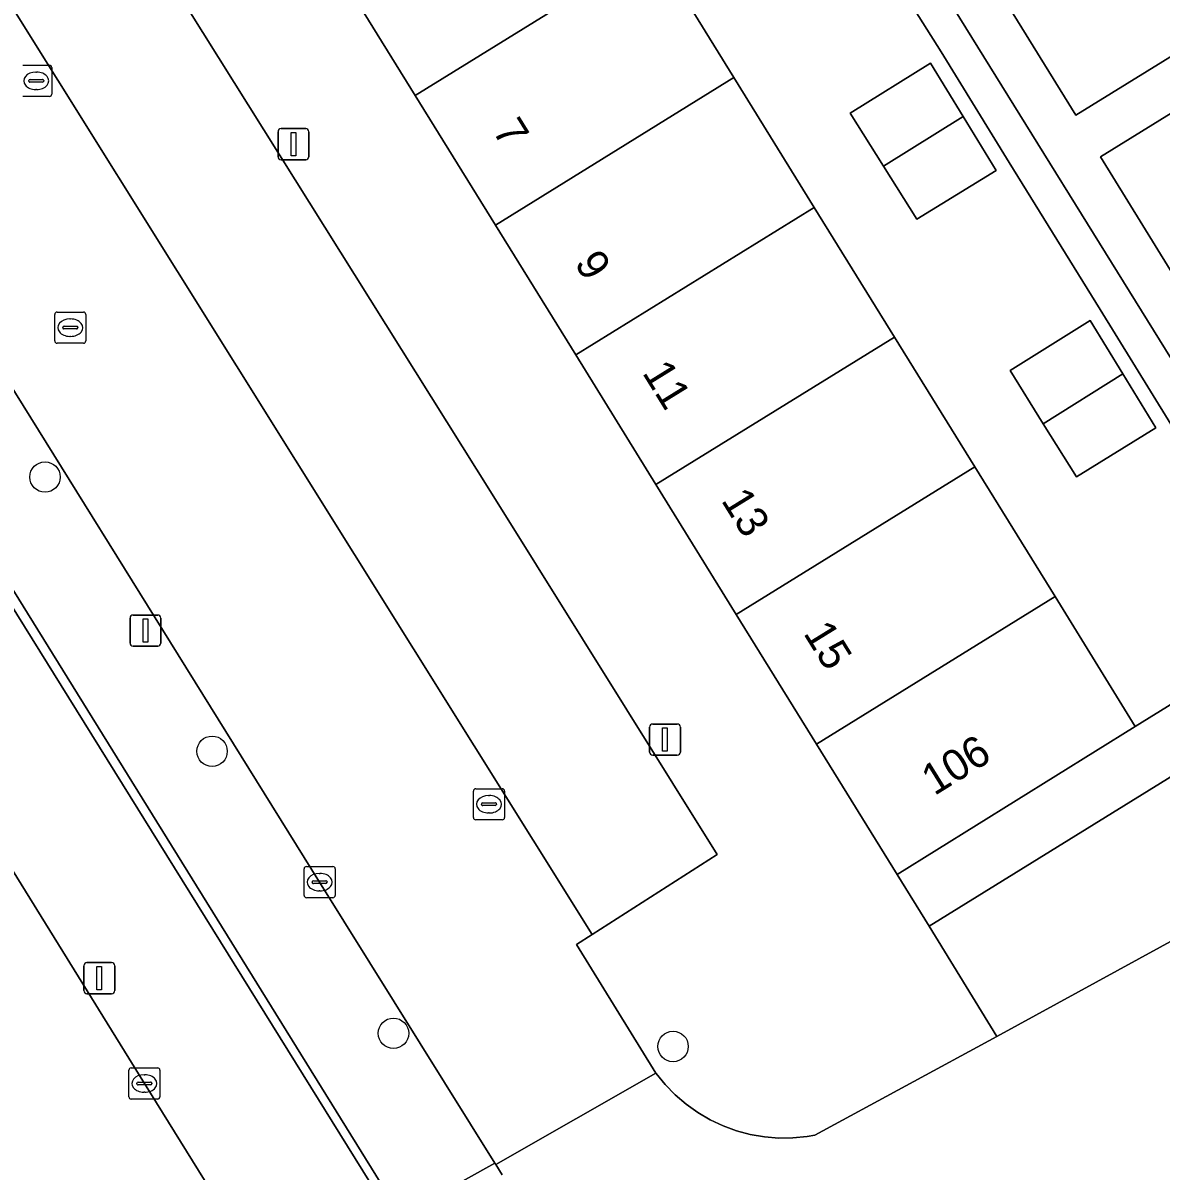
# Model space of a CAD drawing. Extents: x 159888 to 160761, y 384031 to 384750.
# Drawn here: x 160129.59 to 160166.14, y 384502.47 to 384539.34 of the extents above; entities that cross this region are included whole.
import ezdxf

# ---------------------------------------------------------------- set-up
doc = ezdxf.new("R2010")
doc.units = 0
for name, color, linetype in [('IMGEO_Boom', 7, 'Continuous'), ('IMGEO_Erf', 7, 'Continuous'), ('IMGEO_Groenvoorziening', 7, 'Continuous'), ('IMGEO_Haag', 7, 'Continuous'), ('IMGEO_Kolk', 7, 'Continuous'), ('IMGEO_Lichtmast', 7, 'Continuous'), ('IMGEO_Pand', 7, 'Continuous'), ('IMGEO_Pand_nummerreeks', 7, 'Continuous'), ('IMGEO_Parkeervlak_open', 7, 'Continuous'), ('IMGEO_Rijbaan_lokaal_open', 7, 'Continuous'), ('IMGEO_Rioolput', 7, 'Continuous'), ('IMGEO_Voetpad_open', 7, 'Continuous')]:
    doc.layers.add(name, color=color, linetype=linetype)

msp = doc.modelspace()

# ---------------------------------------------------------------- linework, layer by layer
at = {"layer": 'IMGEO_Boom'}
for centre in [(160130.298, 384524.756), (160135.663, 384515.948), (160141.488, 384506.89), (160150.467, 384506.467)]:
    msp.add_circle(centre, 0.489, dxfattribs=at)
at = {"layer": 'IMGEO_Erf'}
for points in [[(160159.072, 384538.41), (160156.136, 384543.082), (160153.968, 384546.63), (160151.058, 384551.349), (160148.865, 384554.895), (160147.274, 384557.486), (160142.113, 384554.255), (160144.691, 384550.087), (160147.268, 384545.92), (160149.846, 384541.752), (160152.424, 384537.585), (160155.001, 384533.417), (160157.579, 384529.25), (160160.157, 384525.082), (160162.734, 384520.915), (160165.312, 384516.747), (160170.363, 384519.868), (160170.433, 384519.911), (160169.216, 384521.94), (160166.364, 384526.593), (160164.187, 384530.138), (160161.258, 384534.862)], [(160158.731, 384538.051), (160159.78, 384536.34), (160160.844, 384534.605), (160158.297, 384533.034), (160157.227, 384534.74), (160156.158, 384536.445)], [(160163.861, 384529.78), (160164.91, 384528.069), (160165.974, 384526.334), (160163.427, 384524.763), (160162.357, 384526.469), (160161.288, 384528.174)]]:
    msp.add_lwpolyline(points, close=True, dxfattribs=at)
at = {"layer": 'IMGEO_Groenvoorziening'}
for points in [[(160189.322, 384578.257), (160186.066, 384583.561), (160185.149, 384585.056), (160180.644, 384582.188), (160181.266, 384581.183), (160148.281, 384560.789), (160152.94, 384553.3), (160163.406, 384536.375), (160200.868, 384559.503)], [(160094.988, 384567.618), (160096.471, 384568.491), (160105.983, 384553.196), (160104.128, 384552.06), (160108.052, 384545.783), (160111.339, 384547.799), (160113.651, 384544.027), (160114.383, 384544.49), (160140.747, 384502.072), (160137.467, 384500), (160136.964, 384499.682), (160134.865, 384498.396), (160135.403, 384497.521), (160139.861, 384500), (160141.73, 384501.039), (160111.559, 384549.71), (160109.049, 384548.124), (160107.46, 384550.64), (160109.97, 384552.226), (160098.429, 384570.771), (160094.502, 384568.326)]]:
    msp.add_lwpolyline(points, dxfattribs=at)
for points in [[(160167.391, 384535.745), (160169.984, 384537.335), (160173.521, 384539.537), (160178.213, 384542.424), (160181.751, 384544.625), (160186.466, 384547.528), (160189.978, 384549.717), (160194.673, 384552.612), (160198.249, 384554.781), (160202.905, 384557.7), (160206.438, 384559.861), (160211.144, 384562.778), (160214.703, 384564.976), (160217.276, 384566.598), (160217.169, 384566.771), (160216.709, 384567.521), (160214.269, 384566.02), (160201.679, 384558.218), (160164.199, 384535.04), (160170.426, 384524.933), (160172.677, 384521.294), (160175.354, 384522.92), (160170.612, 384530.605), (160167.622, 384535.376)], [(160142.113, 384554.255), (160147.274, 384557.486), (160148.865, 384554.895), (160151.058, 384551.349), (160153.968, 384546.63), (160156.136, 384543.082), (160159.072, 384538.41), (160161.258, 384534.862), (160164.187, 384530.138), (160166.364, 384526.593), (160169.216, 384521.94), (160170.433, 384519.911), (160170.652, 384520.047), (160171.445, 384520.533), (160169.806, 384523.173), (160156.159, 384545.179), (160147, 384559.992), (160133.251, 384551.488), (160134.463, 384549.497)], [(160169.305, 384511.405), (160170.4, 384512.003), (160175.06, 384514.551), (160173.984, 384516.264), (160171.292, 384514.598), (160169.658, 384517.108), (160158.688, 384510.331), (160160.869, 384506.792)]]:
    msp.add_lwpolyline(points, close=True, dxfattribs=at)
at = {"layer": 'IMGEO_Haag'}
msp.add_lwpolyline([(160094.988, 384567.618), (160096.471, 384568.491), (160105.983, 384553.196), (160104.128, 384552.06), (160108.052, 384545.783), (160111.339, 384547.799), (160113.651, 384544.027), (160114.383, 384544.49), (160140.747, 384502.072), (160137.467, 384500), (160136.964, 384499.682), (160134.865, 384498.396), (160135.403, 384497.521), (160139.861, 384500), (160141.73, 384501.039), (160111.559, 384549.71), (160109.049, 384548.124), (160107.46, 384550.64), (160109.97, 384552.226), (160098.429, 384570.771), (160094.502, 384568.326)], dxfattribs=at)
at = {"layer": 'IMGEO_Kolk'}
for p, q in [((160129.59, 384537.981), (160130.442, 384537.981)), ((160130.003, 384537.761), (160130.028, 384537.761)), ((160130.516, 384537.907), (160130.516, 384537.055)), ((160129.774, 384537.475), (160129.774, 384537.487)), ((160130.212, 384537.438), (160129.814, 384537.438)), ((160129.817, 384537.524), (160130.215, 384537.524)), ((160130.026, 384537.201), (160130.001, 384537.201)), ((160130.258, 384537.487), (160130.258, 384537.475)), ((160130.442, 384536.981), (160129.59, 384536.981)), ((160144.129, 384514.746), (160144.981, 384514.746)), ((160144.054, 384513.82), (160144.054, 384514.672)), ((160144.542, 384514.526), (160144.567, 384514.526)), ((160145.055, 384514.672), (160145.055, 384513.82)), ((160144.313, 384514.24), (160144.313, 384514.252)), ((160144.751, 384514.203), (160144.353, 384514.203)), ((160144.356, 384514.289), (160144.754, 384514.289)), ((160144.565, 384513.966), (160144.54, 384513.966)), ((160144.797, 384514.252), (160144.797, 384514.24)), ((160144.981, 384513.746), (160144.129, 384513.746)), ((160138.616, 384511.32), (160138.616, 384512.172)), ((160138.691, 384512.246), (160139.543, 384512.246)), ((160139.617, 384512.172), (160139.617, 384511.32)), ((160138.875, 384511.74), (160138.875, 384511.752)), ((160138.918, 384511.789), (160139.316, 384511.789)), ((160139.104, 384512.026), (160139.129, 384512.026)), ((160139.359, 384511.752), (160139.359, 384511.74)), ((160139.313, 384511.703), (160138.915, 384511.703)), ((160139.127, 384511.466), (160139.102, 384511.466)), ((160139.543, 384511.246), (160138.691, 384511.246)), ((160132.989, 384504.852), (160132.989, 384505.704)), ((160133.064, 384505.778), (160133.916, 384505.778)), ((160133.477, 384505.558), (160133.502, 384505.558)), ((160133.99, 384505.704), (160133.99, 384504.852)), ((160133.248, 384505.272), (160133.248, 384505.284)), ((160133.686, 384505.235), (160133.288, 384505.235)), ((160133.291, 384505.321), (160133.689, 384505.321)), ((160133.732, 384505.284), (160133.732, 384505.272)), ((160133.916, 384504.778), (160133.064, 384504.778)), ((160133.5, 384504.998), (160133.475, 384504.998))]:
    msp.add_line(p, q, dxfattribs=at)
for points in [[(160129.59, 384537.981), (160130.442, 384537.981)], [(160130.516, 384537.907), (160130.516, 384537.055)], [(160130.442, 384536.981), (160129.59, 384536.981)], [(160144.129, 384514.746), (160144.981, 384514.746)], [(160144.054, 384513.82), (160144.054, 384514.672)], [(160145.055, 384514.672), (160145.055, 384513.82)], [(160144.981, 384513.746), (160144.129, 384513.746)], [(160138.616, 384511.32), (160138.616, 384512.172)], [(160138.691, 384512.246), (160139.543, 384512.246)], [(160139.617, 384512.172), (160139.617, 384511.32)], [(160139.543, 384511.246), (160138.691, 384511.246)], [(160132.989, 384504.852), (160132.989, 384505.704)], [(160133.064, 384505.778), (160133.916, 384505.778)], [(160133.99, 384505.704), (160133.99, 384504.852)], [(160133.916, 384504.778), (160133.064, 384504.778)]]:
    msp.add_lwpolyline(points, dxfattribs=at)
for centre, radius, start, end in [((160130.44, 384537.905), 0.0765, 1.552, 88.448), ((160130.44, 384537.905), 0.0765, 1.552, 88.448), ((160129.814, 384537.484), 0.0403, 85.8775, 175.7526), ((160129.811, 384537.474), 0.0366, 178.938, 274.7102), ((160130.215, 384537.481), 0.043, 264.8664, 352.4533), ((160130.219, 384537.486), 0.0386, 1.7309, 96.639), ((160130.44, 384537.057), 0.0765, 271.552, 358.448), ((160130.44, 384537.057), 0.0765, 271.552, 358.448), ((160144.131, 384514.67), 0.0765, 91.552, 178.448), ((160144.131, 384514.67), 0.0765, 91.552, 178.448), ((160144.979, 384514.67), 0.0765, 1.552, 88.448), ((160144.979, 384514.67), 0.0765, 1.552, 88.448), ((160144.353, 384514.249), 0.0403, 85.8775, 175.7526), ((160144.35, 384514.239), 0.0366, 178.938, 274.7102), ((160144.754, 384514.246), 0.043, 264.8664, 352.4533), ((160144.758, 384514.251), 0.0386, 1.7309, 96.639), ((160144.131, 384513.822), 0.0765, 181.552, 268.448), ((160144.131, 384513.822), 0.0765, 181.552, 268.448), ((160144.979, 384513.822), 0.0765, 271.552, 358.448), ((160144.979, 384513.822), 0.0765, 271.552, 358.448), ((160138.693, 384512.17), 0.0765, 91.552, 178.448), ((160138.693, 384512.17), 0.0765, 91.552, 178.448), ((160139.541, 384512.17), 0.0765, 1.552, 88.448), ((160139.541, 384512.17), 0.0765, 1.552, 88.448), ((160138.915, 384511.749), 0.0403, 85.8775, 175.7526), ((160139.32, 384511.751), 0.0386, 1.7309, 96.639), ((160138.912, 384511.739), 0.0366, 178.938, 274.7102), ((160139.316, 384511.746), 0.043, 264.8664, 352.4533), ((160138.693, 384511.322), 0.0765, 181.552, 268.448), ((160138.693, 384511.322), 0.0765, 181.552, 268.448), ((160139.541, 384511.322), 0.0765, 271.552, 358.448), ((160139.541, 384511.322), 0.0765, 271.552, 358.448), ((160133.066, 384505.702), 0.0765, 91.552, 178.448), ((160133.066, 384505.702), 0.0765, 91.552, 178.448), ((160133.914, 384505.702), 0.0765, 1.552, 88.448), ((160133.914, 384505.702), 0.0765, 1.552, 88.448), ((160133.288, 384505.281), 0.0403, 85.8775, 175.7526), ((160133.285, 384505.271), 0.0366, 178.938, 274.7102), ((160133.689, 384505.278), 0.043, 264.8664, 352.4533), ((160133.693, 384505.283), 0.0386, 1.7309, 96.639), ((160133.066, 384504.854), 0.0765, 181.552, 268.448), ((160133.066, 384504.854), 0.0765, 181.552, 268.448), ((160133.914, 384504.854), 0.0765, 271.552, 358.448), ((160133.914, 384504.854), 0.0765, 271.552, 358.448)]:
    msp.add_arc(centre, radius, start, end, dxfattribs=at)
for centre, major_axis, ratio, start_param, end_param in [((160130.002, 384537.481), (-0.387, 0.002), 0.722429, 4.712389, 7.853982), ((160130.027, 384537.481), (-0.39, 0.002), 0.717154, 1.570796, 4.712389), ((160144.541, 384514.246), (-0.387, 0.002), 0.722429, 4.712389, 7.853982), ((160144.566, 384514.246), (-0.39, 0.002), 0.717154, 1.570796, 4.712389), ((160139.103, 384511.746), (-0.387, 0.002), 0.722429, 4.712389, 7.853982), ((160139.128, 384511.746), (-0.39, 0.002), 0.717154, 1.570796, 4.712389), ((160133.476, 384505.278), (-0.387, 0.002), 0.722429, 4.712389, 7.853982), ((160133.501, 384505.278), (-0.39, 0.002), 0.717154, 1.570796, 4.712389)]:
    msp.add_ellipse(centre, major_axis=major_axis, ratio=ratio, start_param=start_param, end_param=end_param, dxfattribs=at)
at = {"layer": 'IMGEO_Lichtmast'}
for p, q in [((160137.782, 384535.045), (160137.782, 384535.845)), ((160137.782, 384535.845), (160137.782, 384535.045)), ((160137.882, 384535.945), (160138.672, 384535.945)), ((160138.672, 384535.945), (160137.882, 384535.945)), ((160138.772, 384535.845), (160138.772, 384535.045)), ((160138.772, 384535.045), (160138.772, 384535.845)), ((160138.672, 384534.945), (160137.882, 384534.945)), ((160137.882, 384534.945), (160138.672, 384534.945)), ((160133.129, 384520.323), (160133.919, 384520.323)), ((160133.919, 384520.323), (160133.129, 384520.323)), ((160133.029, 384519.423), (160133.029, 384520.223)), ((160133.029, 384520.223), (160133.029, 384519.423)), ((160134.019, 384520.223), (160134.019, 384519.423)), ((160134.019, 384519.423), (160134.019, 384520.223)), ((160133.919, 384519.323), (160133.129, 384519.323)), ((160133.129, 384519.323), (160133.919, 384519.323)), ((160149.713, 384515.923), (160149.713, 384516.723)), ((160149.713, 384516.723), (160149.713, 384515.923)), ((160149.813, 384516.823), (160150.603, 384516.823)), ((160150.603, 384516.823), (160149.813, 384516.823)), ((160150.703, 384516.723), (160150.703, 384515.923)), ((160150.703, 384515.923), (160150.703, 384516.723)), ((160150.603, 384515.823), (160149.813, 384515.823)), ((160149.813, 384515.823), (160150.603, 384515.823)), ((160131.546, 384508.261), (160131.546, 384509.061)), ((160131.546, 384509.061), (160131.546, 384508.261)), ((160131.646, 384509.161), (160132.436, 384509.161)), ((160132.436, 384509.161), (160131.646, 384509.161)), ((160132.536, 384509.061), (160132.536, 384508.261)), ((160132.536, 384508.261), (160132.536, 384509.061)), ((160132.436, 384508.161), (160131.646, 384508.161)), ((160131.646, 384508.161), (160132.436, 384508.161))]:
    msp.add_line(p, q, dxfattribs=at)
for points in [[(160138.202, 384535.82), (160138.352, 384535.82), (160138.352, 384535.07), (160138.202, 384535.07), (160138.202, 384535.82)], [(160133.449, 384520.198), (160133.599, 384520.198), (160133.599, 384519.448), (160133.449, 384519.448), (160133.449, 384520.198)], [(160150.133, 384516.698), (160150.283, 384516.698), (160150.283, 384515.948), (160150.133, 384515.948), (160150.133, 384516.698)], [(160131.966, 384509.036), (160132.116, 384509.036), (160132.116, 384508.286), (160131.966, 384508.286), (160131.966, 384509.036)]]:
    msp.add_lwpolyline(points, dxfattribs=at)
for centre, start, end in [((160137.882, 384535.845), 90, 180), ((160137.882, 384535.845), 90, 180), ((160138.672, 384535.845), 0, 90), ((160138.672, 384535.845), 360, 90), ((160137.882, 384535.045), 180, 270), ((160137.882, 384535.045), 180, 270), ((160138.672, 384535.045), 270, 0), ((160138.672, 384535.045), 270, 0), ((160133.129, 384520.223), 90, 180), ((160133.129, 384520.223), 90, 180), ((160133.919, 384520.223), 0, 90), ((160133.919, 384520.223), 360, 90), ((160133.129, 384519.423), 180, 270), ((160133.129, 384519.423), 180, 270), ((160133.919, 384519.423), 270, 0), ((160133.919, 384519.423), 270, 0), ((160149.813, 384516.723), 90, 180), ((160149.813, 384516.723), 90, 180), ((160150.603, 384516.723), 0, 90), ((160150.603, 384516.723), 360, 90), ((160149.813, 384515.923), 180, 270), ((160149.813, 384515.923), 180, 270), ((160150.603, 384515.923), 270, 0), ((160150.603, 384515.923), 270, 0), ((160131.646, 384509.061), 90, 180), ((160131.646, 384509.061), 90, 180), ((160132.436, 384509.061), 0, 90), ((160132.436, 384509.061), 360, 90), ((160131.646, 384508.261), 180, 270), ((160131.646, 384508.261), 180, 270), ((160132.436, 384508.261), 270, 0), ((160132.436, 384508.261), 270, 0)]:
    msp.add_arc(centre, 0.1, start, end, dxfattribs=at)
at = {"layer": 'IMGEO_Pand'}
for points in [[(160147.268, 384545.92), (160139.607, 384541.181), (160142.185, 384537.014), (160149.846, 384541.752)], [(160149.846, 384541.752), (160142.185, 384537.014), (160144.763, 384532.847), (160152.424, 384537.585)], [(160156.158, 384536.445), (160157.227, 384534.74), (160159.78, 384536.34), (160158.731, 384538.051)], [(160152.424, 384537.585), (160144.763, 384532.847), (160147.341, 384528.679), (160155.001, 384533.417)], [(160159.78, 384536.34), (160157.227, 384534.74), (160158.297, 384533.034), (160160.844, 384534.605)], [(160155.001, 384533.417), (160147.341, 384528.679), (160149.919, 384524.512), (160157.579, 384529.25)], [(160161.288, 384528.174), (160162.357, 384526.469), (160164.91, 384528.069), (160163.861, 384529.78)], [(160157.579, 384529.25), (160149.919, 384524.512), (160152.497, 384520.345), (160160.157, 384525.082)], [(160164.91, 384528.069), (160162.357, 384526.469), (160163.427, 384524.763), (160165.974, 384526.334)], [(160160.157, 384525.082), (160152.497, 384520.345), (160155.075, 384516.177), (160162.734, 384520.915)], [(160162.734, 384520.915), (160155.075, 384516.177), (160157.662, 384511.995), (160165.312, 384516.747)]]:
    msp.add_lwpolyline(points, close=True, dxfattribs=at)
at = {"layer": 'IMGEO_Parkeervlak_open'}
msp.add_lwpolyline([(160117.379, 384558.808), (160147.868, 384510.063), (160151.885, 384512.636), (160144.66, 384524.211), (160133.91, 384541.367), (160121.735, 384560.901), (160119.572, 384559.594), (160117.97, 384558.646)], dxfattribs=at)
msp.add_lwpolyline([(160110.676, 384542.144), (160117.707, 384530.736), (160125.564, 384518.085), (160133.491, 384505.278), (160136.767, 384500), (160136.964, 384499.682), (160137.467, 384500), (160140.747, 384502.072), (160114.383, 384544.49), (160113.651, 384544.027)], close=True, dxfattribs=at)
at = {"layer": 'IMGEO_Rijbaan_lokaal_open'}
for points in [[(160102.306, 384570.763), (160113.563, 384552.653), (160125.049, 384534.359), (160139.118, 384511.747), (160144.747, 384502.719), (160144.775, 384502.674), (160149.919, 384505.608), (160147.362, 384509.739), (160147.868, 384510.063), (160117.379, 384558.808), (160117.159, 384559.167), (160108.137, 384573.672)], [(160136.767, 384500), (160133.491, 384505.278), (160125.564, 384518.085), (160117.707, 384530.736), (160110.676, 384542.144), (160110.423, 384541.989), (160108.052, 384545.783), (160104.128, 384552.06), (160094.396, 384567.694)], [(160165.309, 384500), (160173.174, 384504.351), (160169.437, 384511.163), (160169.305, 384511.405), (160160.869, 384506.792), (160155.019, 384503.618), (160154.776, 384503.572), (160154.318, 384503.528), (160153.859, 384503.525), (160153.4, 384503.563), (160152.947, 384503.642), (160152.503, 384503.761), (160152.071, 384503.919), (160151.655, 384504.115), (160151.259, 384504.348), (160150.884, 384504.615), (160150.535, 384504.914), (160150.214, 384505.243), (160149.924, 384505.6), (160149.919, 384505.608), (160144.775, 384502.674), (160144.978, 384502.349)]]:
    msp.add_lwpolyline(points, dxfattribs=at)
at = {"layer": 'IMGEO_Rioolput'}
for p, q in [((160130.608, 384529.128), (160130.608, 384529.98)), ((160130.683, 384530.054), (160131.535, 384530.054)), ((160131.096, 384529.834), (160131.121, 384529.834)), ((160131.609, 384529.98), (160131.609, 384529.128)), ((160130.867, 384529.548), (160130.867, 384529.56)), ((160131.305, 384529.511), (160130.907, 384529.511)), ((160130.91, 384529.597), (160131.308, 384529.597)), ((160131.351, 384529.56), (160131.351, 384529.548)), ((160131.119, 384529.274), (160131.094, 384529.274)), ((160131.535, 384529.054), (160130.683, 384529.054))]:
    msp.add_line(p, q, dxfattribs=at)
for points in [[(160130.608, 384529.128), (160130.608, 384529.98)], [(160130.683, 384530.054), (160131.535, 384530.054)], [(160131.609, 384529.98), (160131.609, 384529.128)], [(160131.535, 384529.054), (160130.683, 384529.054)]]:
    msp.add_lwpolyline(points, dxfattribs=at)
for centre, radius, start, end in [((160130.685, 384529.978), 0.0765, 91.552, 178.448), ((160130.685, 384529.978), 0.0765, 91.552, 178.448), ((160131.533, 384529.978), 0.0765, 1.552, 88.448), ((160131.533, 384529.978), 0.0765, 1.552, 88.448), ((160130.907, 384529.557), 0.0403, 85.8775, 175.7526), ((160130.904, 384529.547), 0.0366, 178.938, 274.7102), ((160131.308, 384529.554), 0.043, 264.8664, 352.4533), ((160131.312, 384529.559), 0.0386, 1.7309, 96.639), ((160130.685, 384529.13), 0.0765, 181.552, 268.448), ((160130.685, 384529.13), 0.0765, 181.552, 268.448), ((160131.533, 384529.13), 0.0765, 271.552, 358.448), ((160131.533, 384529.13), 0.0765, 271.552, 358.448)]:
    msp.add_arc(centre, radius, start, end, dxfattribs=at)
for centre, major_axis, ratio, start_param, end_param in [((160131.095, 384529.554), (-0.387, 0.002), 0.722429, 4.712389, 7.853982), ((160131.12, 384529.554), (-0.39, 0.002), 0.717154, 1.570796, 4.712389)]:
    msp.add_ellipse(centre, major_axis=major_axis, ratio=ratio, start_param=start_param, end_param=end_param, dxfattribs=at)
at = {"layer": 'IMGEO_Voetpad_open'}
for points in [[(160201.865, 384560.132), (160178.233, 384599.071), (160177.796, 384599.792), (160176.521, 384599.021), (160184.387, 384586.273), (160184.426, 384586.21), (160181.762, 384584.546), (160180.262, 384583.57), (160179.199, 384582.937), (160178.648, 384582.593), (160179.214, 384581.669), (160139.949, 384557.419), (160132.473, 384552.799), (160133.251, 384551.488), (160147, 384559.992), (160156.159, 384545.179), (160169.806, 384523.173), (160171.445, 384520.533), (160172.677, 384521.294), (160170.426, 384524.933), (160164.199, 384535.04), (160201.679, 384558.218)], [(160099.535, 384571.453), (160098.429, 384570.771), (160109.97, 384552.226), (160111.559, 384549.71), (160141.73, 384501.039), (160144.747, 384502.719), (160139.118, 384511.747), (160125.049, 384534.359), (160113.563, 384552.653)], [(160133.91, 384541.367), (160144.66, 384524.211), (160151.885, 384512.636), (160147.868, 384510.063), (160147.362, 384509.739), (160149.919, 384505.608), (160149.924, 384505.6), (160150.214, 384505.243), (160150.535, 384504.914), (160150.884, 384504.615), (160151.259, 384504.348), (160151.655, 384504.115), (160152.071, 384503.919), (160152.503, 384503.761), (160152.947, 384503.642), (160153.4, 384503.563), (160153.859, 384503.525), (160154.318, 384503.528), (160154.776, 384503.572), (160155.019, 384503.618), (160160.869, 384506.792), (160158.688, 384510.331), (160157.662, 384511.995), (160155.075, 384516.177), (160152.497, 384520.345), (160149.919, 384524.512), (160147.341, 384528.679), (160144.763, 384532.847), (160142.185, 384537.014), (160139.607, 384541.181)], [(160187.822, 384530.635), (160183.668, 384528.065), (160179.515, 384525.495), (160178.674, 384524.974), (160175.354, 384522.92), (160172.677, 384521.294), (160171.445, 384520.533), (160170.652, 384520.047), (160170.433, 384519.911), (160170.363, 384519.868), (160165.312, 384516.747), (160157.662, 384511.995), (160158.688, 384510.331), (160169.658, 384517.108), (160171.292, 384514.598), (160173.984, 384516.264), (160175.06, 384514.551), (160177.571, 384516.068)], [(160144.978, 384502.349), (160144.775, 384502.674), (160144.747, 384502.719), (160141.73, 384501.039), (160139.861, 384500), (160135.403, 384497.521), (160136.49, 384495.754)]]:
    msp.add_lwpolyline(points, dxfattribs=at)
msp.add_lwpolyline([(160196.17, 384567.098), (160200.122, 384560.709), (160200.868, 384559.503), (160163.406, 384536.375), (160152.94, 384553.3), (160148.281, 384560.789), (160181.266, 384581.183), (160180.644, 384582.188), (160185.149, 384585.056), (160186.066, 384583.561), (160189.322, 384578.257)], close=True, dxfattribs=at)

# ---------------------------------------------------------------- texts
at = {"layer": 'IMGEO_Pand_nummerreeks'}
for s, rotation, p in [('7', 301.7417, (160144.649, 384535.881)), ('9', 301.7417, (160147.281, 384531.627)), ('11', 301.7417, (160149.46, 384528.106)), ('13', 301.7417, (160151.994, 384524.008)), ('15', 301.7417, (160154.634, 384519.74)), ('106', 31.845, (160158.856, 384514.503))]:
    msp.add_text(s, height=1, rotation=rotation, dxfattribs=at).set_placement(p)

doc.saveas('drawing.dxf')
